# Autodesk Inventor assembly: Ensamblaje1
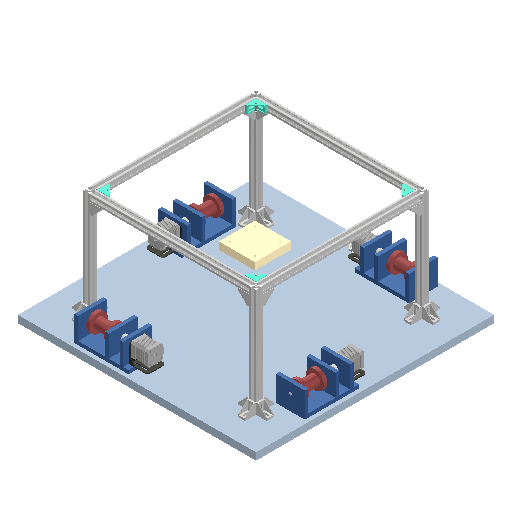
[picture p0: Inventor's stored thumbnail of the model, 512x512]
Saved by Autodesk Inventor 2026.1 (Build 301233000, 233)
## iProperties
Created: 2025-06
Part Number: Ensamblaje1
Document SubType Name: Assembly
Designer: piero
Author: piero
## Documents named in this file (9)
- D:\Tesis\Modelo 3D\CAD\Ensamblaje1.iam
- D:\Tesis\Modelo 3D\CAD\Mesa.ipt
- D:\Tesis\Modelo 3D\CAD\V-slot.ipt
- D:\Tesis\Modelo 3D\CAD\Ensamblaje2.iam
- D:\Tesis\Modelo 3D\CAD\Plataforma.ipt
- D:\Tesis\Modelo 3D\CAD\Esquinero.ipt
- D:\Tesis\Modelo 3D\CAD\V-slot_2.ipt
- D:\Tesis\Modelo 3D\CAD\Soporte gancho.ipt
- D:\Tesis\Modelo 3D\CAD\Gancho.ipt
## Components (46 placed, 8 different names)
1. Mesa:1
2. V-slot:1
3. V-slot:2 — Nivelación:9, Nivelación:10, Coincidencia:5, Coincidencia:6, Nivelación:11, Nivelación:12
4. V-slot:3 — Coincidencia:7, Coincidencia:8, Coincidencia:9
5. V-slot:4 — Nivelación:1, Nivelación:2, Coincidencia:1, Nivelación:3, Nivelación:4, Coincidencia:2, Coincidencia:10
6. Plataforma:1
7. V-slot_2:1
8. V-slot_2:2 — Nivelación:1, Nivelación:2, Coincidencia:1, Coincidencia:8, Coincidencia:9
9. V-slot_2:3 — Coincidencia:6, Nivelación:11, Nivelación:12, Coincidencia:7
10. V-slot_2:4
11. Esquinero:6 — Coincidencia:13, Nivelación:14, Coincidencia:14
12. Esquinero:5 — Coincidencia:11, Nivelación:13, Coincidencia:12
13. Ensamblaje2:1 [sub-assembly] — Coincidencia:22
14. Soporte gancho:1 — Nivelación:16, Coincidencia:27, Coincidencia:28, Coincidencia:29
15. Gancho:1 — Coincidencia:29
16. Esquinero:11
17. Esquinero:12
18. Ensamblaje2:2 [sub-assembly]
19. Soporte gancho:2
20. Gancho:2
21. Esquinero:17
22. Esquinero:18
23. Ensamblaje2:3 [sub-assembly]
24. Soporte gancho:3
25. Gancho:3
26. Esquinero:23
27. Esquinero:24
28. Ensamblaje2:4 [sub-assembly]
29. Soporte gancho:4
30. Gancho:4
31. Esquinero:7 — Coincidencia:25, Nivelación:15, Coincidencia:26
32. Esquinero:8
33. Esquinero:9
34. Esquinero:10
35. Esquinero:13
36. Esquinero:14
37. Esquinero:15
38. Esquinero:16
39. Esquinero:19
40. Esquinero:20
41. Esquinero:21
42. Esquinero:22
43. Esquinero:25
44. Esquinero:26
45. Esquinero:27
46. Esquinero:28
## Component patterns: Patrón de componentes 2:2 (4 elements), Patrón de componentes 2:3 (4 elements), Patrón de componentes 2:4 (4 elements)
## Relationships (30: Mate 18, Flush 12)
- Nivelación:1 [Flush]: V-slot:4 ↔ V-slot_2:2
- Nivelación:2 [Flush]: V-slot:4 ↔ V-slot_2:2
- Coincidencia:1 [Mate]: V-slot:4 ↔ V-slot_2:2
- Nivelación:3 [Flush]: V-slot:4
- Nivelación:4 [Flush]: V-slot:4
- Coincidencia:2 [Mate]: V-slot:4
- Nivelación:9 [Flush]: V-slot:2
- Nivelación:10 [Flush]: V-slot:2
- Coincidencia:5 [Mate]: V-slot:2
- Coincidencia:6 [Mate]: V-slot:2 ↔ V-slot_2:3
- Nivelación:11 [Flush]: V-slot:2 ↔ V-slot_2:3
- Nivelación:12 [Flush]: V-slot:2 ↔ V-slot_2:3
- Coincidencia:7 [Mate]: V-slot:3 ↔ V-slot_2:3
- Coincidencia:8 [Mate]: V-slot:3 ↔ V-slot_2:2
- Coincidencia:9 [Mate]: V-slot:3 ↔ V-slot_2:2
- Coincidencia:10 [Mate]: V-slot:4
- Coincidencia:11 [Mate]: Esquinero:5
- Nivelación:13 [Flush]: Esquinero:5
- Coincidencia:12 [Mate]: Esquinero:5
- Coincidencia:13 [Mate]: Esquinero:6
- Nivelación:14 [Flush]: Esquinero:6
- Coincidencia:14 [Mate]: Esquinero:6
- Coincidencia:22 [Mate]: Ensamblaje2:1
- Coincidencia:25 [Mate]: Esquinero:7
- Nivelación:15 [Flush]: Esquinero:7
- Coincidencia:26 [Mate]: Esquinero:7
- Nivelación:16 [Flush]: Soporte gancho:1
- Coincidencia:27 [Mate]: Soporte gancho:1
- Coincidencia:28 [Mate]: Soporte gancho:1
- Coincidencia:29 [Mate]: Soporte gancho:1 ↔ Gancho:1
